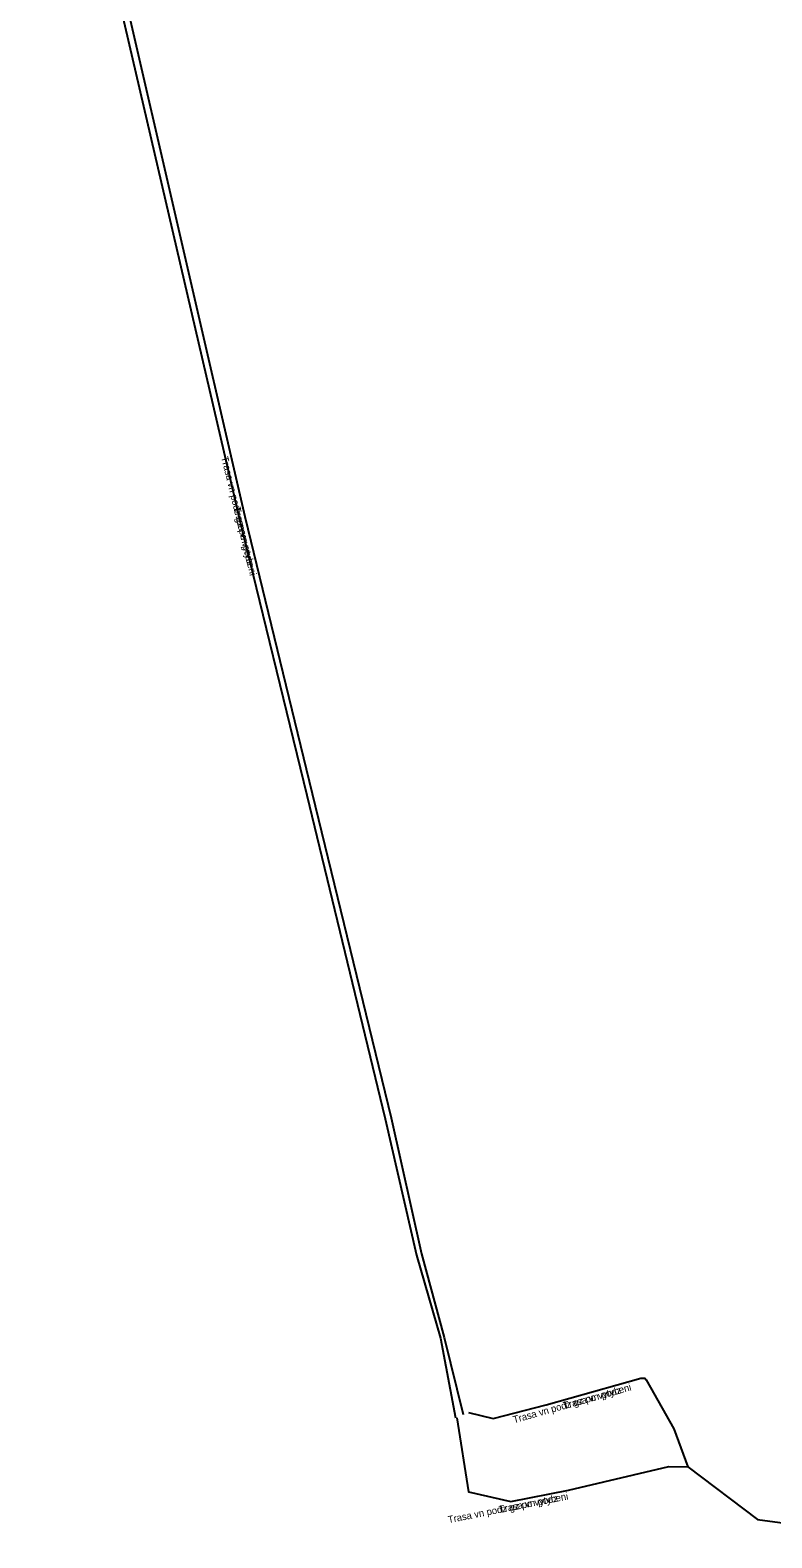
# Model space of a CAD drawing. Extents: x -473162 to -472638, y -1107075 to -1106812.
# Drawn here: x -472922.5 to -472870, y -1107033.1 to -1106926.5 of the extents above; entities that cross this region are included whole.
import ezdxf

# ---------------------------------------------------------------- set-up
doc = ezdxf.new("R2010")
doc.units = 0
doc.layers.add('Popiskový text - Ostatní atributy Trasy', color=7, linetype='Continuous')
doc.layers.add('Spojnice VN', color=7, linetype='Continuous')

msp = doc.modelspace()

# ---------------------------------------------------------------- linework, layer by layer
at = {"layer": 'Spojnice VN'}
for points in [[(-472922.47, -1106902.33), (-472919.06, -1106909.81), (-472917.89, -1106915.23), (-472916.11, -1106922.66), (-472907.28, -1106960.88), (-472902.51, -1106980.47), (-472896.93, -1107003.41), (-472894.77, -1107013.03), (-472893.17, -1107018.95), (-472891.83, -1107024.39)], [(-472922.47, -1106902.33), (-472919.06, -1106909.81), (-472917.89, -1106915.23), (-472916.11, -1106922.66), (-472907.28, -1106960.88), (-472902.51, -1106980.47), (-472896.93, -1107003.41), (-472894.77, -1107013.03), (-472893.17, -1107018.95), (-472891.83, -1107024.39)], [(-472916.55, -1106922.8), (-472907.68, -1106960.98), (-472902.89, -1106980.6), (-472897.36, -1107003.49), (-472895.13, -1107013.14), (-472893.44, -1107019.01), (-472892.38, -1107024.63)], [(-472916.55, -1106922.8), (-472907.68, -1106960.98), (-472902.89, -1106980.6), (-472897.36, -1107003.49), (-472895.13, -1107013.14), (-472893.44, -1107019.01), (-472892.38, -1107024.63)], [(-472875.93, -1107028.1), (-472871, -1107031.82), (-472861.33, -1107033.12), (-472850.8, -1107030.64), (-472845.32, -1107029.36), (-472833.57, -1107026.45), (-472822.85, -1107023.72), (-472815.1, -1107022.25), (-472801.34, -1107019), (-472791.51, -1107016.55), (-472781.55, -1107013.95), (-472772.18, -1107011.27), (-472769.48, -1107010.31), (-472760.41, -1107005.48), (-472750.82, -1106999.47), (-472737.83, -1106992.21), (-472734.32, -1106989.81), (-472728.85, -1106987.34), (-472726.78, -1106986.17), (-472724.29, -1106985.16)], [(-472875.93, -1107028.1), (-472871, -1107031.82), (-472861.33, -1107033.12), (-472850.8, -1107030.64), (-472845.32, -1107029.36), (-472833.57, -1107026.45), (-472822.85, -1107023.72), (-472815.1, -1107022.25), (-472801.34, -1107019), (-472791.51, -1107016.55), (-472781.55, -1107013.95), (-472772.18, -1107011.27), (-472769.48, -1107010.31), (-472760.41, -1107005.48), (-472750.82, -1106999.47), (-472737.83, -1106992.21), (-472734.32, -1106989.81), (-472728.85, -1106987.34), (-472726.78, -1106986.17), (-472724.29, -1106985.16)], [(-472891.45, -1107024.26), (-472889.72, -1107024.68), (-472885.96, -1107023.71), (-472879.26, -1107021.83), (-472878.97, -1107021.83), (-472878.88, -1107021.94), (-472876.93, -1107025.42), (-472875.93, -1107028.1)], [(-472891.45, -1107024.26), (-472889.72, -1107024.68), (-472885.96, -1107023.71), (-472879.26, -1107021.83), (-472878.97, -1107021.83), (-472878.88, -1107021.94), (-472876.93, -1107025.42), (-472875.93, -1107028.1)], [(-472892.27, -1107024.63), (-472891.46, -1107029.86), (-472888.46, -1107030.55), (-472884.38, -1107029.75), (-472877.28, -1107028.08), (-472875.93, -1107028.1)], [(-472892.27, -1107024.63), (-472891.46, -1107029.86), (-472888.46, -1107030.55), (-472884.38, -1107029.75), (-472877.28, -1107028.08), (-472875.93, -1107028.1)]]:
    msp.add_lwpolyline(points, dxfattribs=at)

# ---------------------------------------------------------------- texts
at = {"layer": 'Popiskový text - Ostatní atributy Trasy'}
for s, rotation, p in [('Trasa vn podz gz po vytyceni', 283.6814, (-472908.96, -1106956.69)), ('Trasa vn podz', 283.6814, (-472908.09, -1106960.27)), ('Trasa vn podz gz po vytyceni', 15.6851, (-472888.23, -1107025.02)), ('Trasa vn podz', 15.6851, (-472884.68, -1107024.03)), ('Trasa vn podz gz po vytyceni', 11.2423, (-472892.86, -1107032.09)), ('Trasa vn podz', 11.2423, (-472889.25, -1107031.37))]:
    msp.add_text(s, height=0.5, rotation=rotation, dxfattribs=at).set_placement(p)

doc.saveas('drawing.dxf')
